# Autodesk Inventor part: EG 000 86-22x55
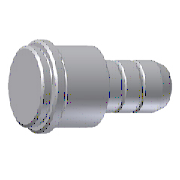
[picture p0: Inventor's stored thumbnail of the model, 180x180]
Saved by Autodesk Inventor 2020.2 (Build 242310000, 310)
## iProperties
Manager: www.cadconsulting.pl
Company: Fabian Stasiak CAD Consulting
IsCustomPart: 0
Created: 2014-02
Part Number: EG 000 86-22x55
Material: DIN 1.7131
Description: Leader Pins
Document SubType Name: Modeling
Designer: F.Stasiak
Standard Revision: 1
Manufacturer: DME
Language: pl-PL
Size Designation: 86-22x55
Categories: <MemberInstance><Categories><Category DisplayName="Forma wtryskowa" InternalName="349578f2-f4d4-4954-8c09-8e99297a61c0" Mnemonic="MOLD"><Category DisplayName="K
Mass: 4.19143 g
Surface Area: 17.8137 cm^2
Volume: 4.19143 cm^3
Density: 7.85 g/cm^3
Appearance: Stal
Catalog Web Link: www.expertbooks.pl
Author: F.Stasiak
Subject: Zbiór ćwiczeń. Autodesk Inventor 2020. Kurs Professional
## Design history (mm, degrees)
sketch "Sketch1"
  geometry: L1 (0, -42.393)-(0, 14.066) reference; L2 (0, 15)-(15, 15); L3 (15, 15)-(15, 7); L4 (14.5, 6)-(17.5, 6); L5 (17.5, 6)-(17.5, 0); L6 (17.5, 0)-(14.5, 0); L7 (15, -1)-(15, -78); L8 (15, -78)-(15, -78); L9 (15, -78)-(15, -80); L10 (15, -80)-(11, -80); L11 (11, -128)-(9.522, -133.518); L12 (7.59, -135)-(0, -135); L13 (11, -80)-(11, -128); L14 (14.5, 0)-(14.5, -1); L15 (14.5, -1)-(15, -1); L16 (14.5, 7)-(15, 7); L17 (14.5, 7)-(14.5, 6); L18 (0, 15)-(0, -135); A1 r 2 centre (7.59, -133) between (7.59, -135) and (9.522, -133.518); 1 further point
  constraints: 38 end point, 7 perpendicular, 6 parallel, 2 collinear, 2 point on circle, 2 point on line, 2 tangent, 2 vertical alignment, 1 centre point, 1 horizontal alignment
  dimensions: "d73" = 6 distance between parallel lines of L6 L4 (derived); "d74" = 9 distance between parallel lines of L2 L4 (derived); "d75" = 86 distance between parallel lines of L10 L4 (derived); "d76" = 2 distance between parallel lines of L10 L8; "d77" = 35 diameter of L5 L1 (derived); "d78" = 55 distance between parallel lines of L12 L10 (derived); "d79" = 30 diameter of L3 L1 (derived); "d89" = 7 distance from line of L12 L11.start (derived); "d92" = 22 diameter of L13 L1 (derived); "d94" = 30 diameter of L7 L1 (derived); "d97" = 2 radius of A1; "d110" = 0.5 distance between parallel lines of L7 L14; "d111" = 1 distance from line of L6.end L15; "d112" = 0.5 distance between parallel lines of L3 L17; "d113" = 1 distance between parallel lines of L4 L16; "d114" = 30 diameter of L9 L18 (derived); "d120" = 15 deg angle of L13 L11
revolve "Revolution1" sketch "Sketch1" stored, may be unused: angle "d100" = 90 deg
chamfer "Chamfer1" distance "d106" = 0.5; stored, may be unused: second distance "d107" = 2, angle "d108" = 45 deg
fillet "Fillet1" dims "d109" = 0.3
sketch "Sketch2"
  geometry: L1 (-7.59, -135)-(7.59, -135) reference; L2 (0, -40.8)-(0, 6.8) reference; C1 r 1.375 at (11.275, -96); C2 r 1.375 at (11.275, -112); 1 further point
  constraints: 2 centre point, 1 equal radius, 1 vertical alignment
  dimensions: "d121" = 2.75 diameter of C1 (derived); "d122" = 23 distance from line of L1 C2.centre (derived); "d123" = 39 distance from line of L1 C1.centre (derived); "d129" = 22.55 diameter of C1.centre L2 (derived)
revolve "Revolution2" sketch "Sketch2" stored, may be unused: angle "d126" = 90 deg
body "Solid1"
other parameters: "d3" = 35 [user parameter], "l2" = 9 [user parameter], "l1" = 6 [user parameter], "A_" = 86 [user parameter], "B" = 55 [user parameter], "d1" = 22 [user parameter; used in 1 equation term], "d43" = 22 (= d1), "d91" = 8, "d101" = 0, "d103" = 0, "ob" = 7 [user parameter], "B1" = 23 [user parameter], "G1" = 39 [user parameter], "d128" = 0, "L_" = 141 [user parameter]
